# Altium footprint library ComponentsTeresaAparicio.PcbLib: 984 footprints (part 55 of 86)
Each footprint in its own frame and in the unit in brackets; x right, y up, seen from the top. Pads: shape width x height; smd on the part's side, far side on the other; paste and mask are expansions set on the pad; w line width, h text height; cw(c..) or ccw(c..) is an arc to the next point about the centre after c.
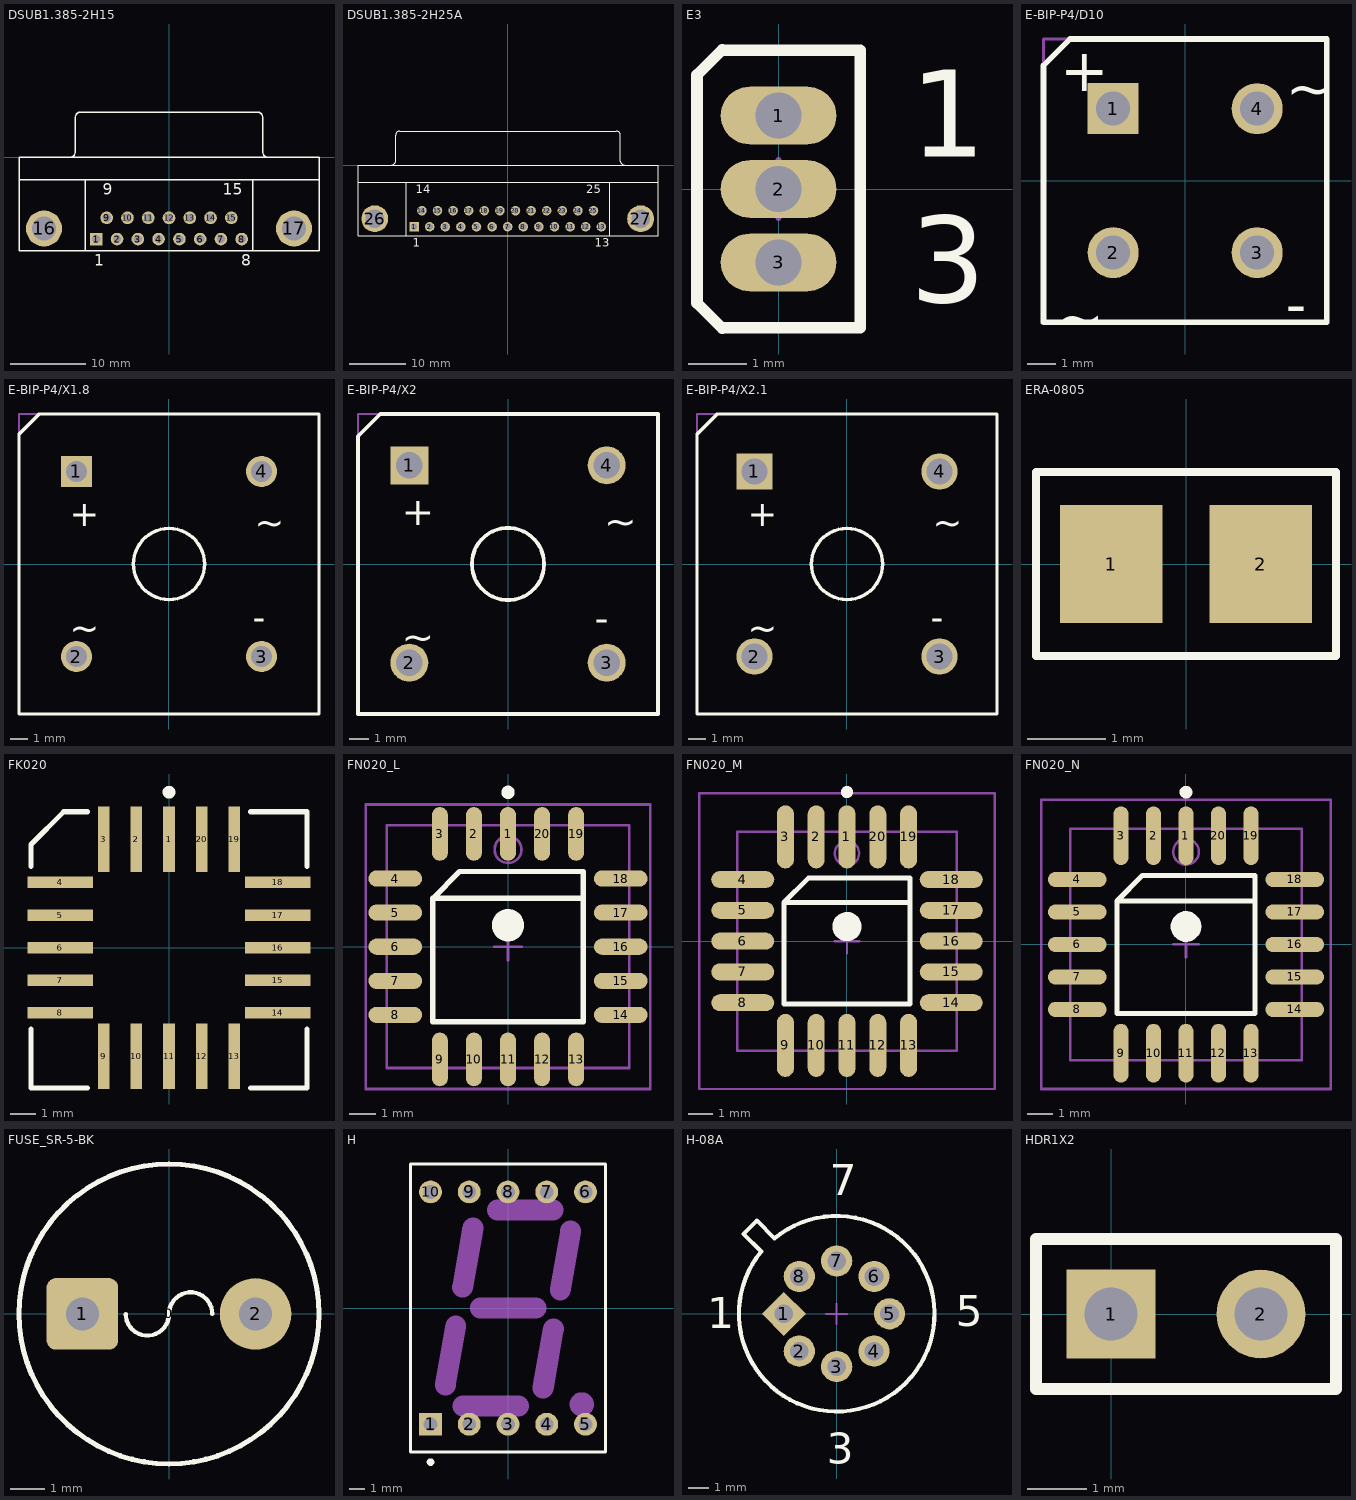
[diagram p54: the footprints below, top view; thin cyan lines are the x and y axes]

## DSUB1.385-2H15 [mm] "Connector; D Subminiature; 15 Position; Right Angle; Pitch 1.385 mm"
height 12.75
pads (17):
  rect 1.69x1.69 hole 1.09: 1(-9.695,-10.92)
  round 1.69 hole 1.09: 2(-6.925,-10.92) 3(-4.155,-10.92) 4(-1.385,-10.92) 5(1.385,-10.92) 6(4.155,-10.92) 7(6.925,-10.92) 8(9.695,-10.92) 9(-8.31,-8.08) 10(-5.54,-8.08) 11(-2.77,-8.08) 12(0,-8.08) 13(2.77,-8.08) 14(5.54,-8.08) 15(8.31,-8.08)
  round 4.8 hole 3.18: 16(-16.66,-9.5) 17(16.66,-9.5)
Top Overlay:
  lines w0.2: -20,-3 20,-3 ; -13.195,0.005 ccw(c-13.195,0.7) -12.5,0.7 -12.5,5.3 ; -12.495,5.305 cw(c-11.8,5.305) -11.8,6 11.8,6 cw(c11.8,5.305) 12.495,5.305 ; -11.14,-12.5 -11.14,-3 ; 11.14,-12.5 11.14,-3 ; 12.5,5.3 12.5,0.7 ccw(c13.195,0.7) 13.195,0.005 ; -20,-12.5 -20,0 20,0 20,-12.5 -20,-12.5
  text "1" at -9.945,-14.475 h1.5
  text "8" at 9.652,-14.475 h1.5
  text "15" at 7.185,-4.975 h1.5
  text "9" at -8.81,-4.975 h1.5

## DSUB1.385-2H25A [mm] "Connector; D Subminiature; 25 Position; Right Angle; Pitch 1.385 mm"
height 12.93
pads (27):
  rect 1.69x1.69 hole 1.09: 1(-16.566,-10.92)
  round 1.69 hole 1.09: 2(-13.805,-10.92) 3(-11.044,-10.92) 4(-8.283,-10.92) 5(-5.522,-10.92) 6(-2.761,-10.92) 7(0,-10.92) 8(2.761,-10.92) 9(5.522,-10.92) 10(8.283,-10.92) 11(11.044,-10.92) 12(13.805,-10.92) 13(16.566,-10.92) 14(-15.185,-8.08) 15(-12.424,-8.08) 16(-9.663,-8.08) 17(-6.902,-8.08) 18(-4.141,-8.08) 19(-1.38,-8.08) 20(1.381,-8.08) 21(4.142,-8.08) 22(6.903,-8.08) 23(9.664,-8.08) 24(12.425,-8.08) 25(15.186,-8.08)
  round 4.76 hole 3.26: 26(-23.526,-9.5) 27(23.526,-9.5)
Top Overlay:
  lines w0.2: -26.496,-3 26.604,-3 ; -20.541,0.005 ccw(c-20.541,0.7) -19.846,0.7 -19.846,5.3 ; -19.841,5.305 cw(c-19.146,5.305) -19.146,6 19.254,6 cw(c19.254,5.305) 19.949,5.305 ; -17.946,-12.5 -17.946,-3 ; 18.054,-12.5 18.054,-3 ; 19.954,5.3 19.954,0.7 ccw(c20.649,0.7) 20.649,0.005 ; -26.496,-12.5 -26.496,0 26.604,0 26.604,-12.5 -26.496,-12.5
  text "25" at 13.936,-4.975 h1.5
  text "14" at -16.31,-4.975 h1.5
  text "13" at 15.441,-14.475 h1.5
  text "1" at -16.816,-14.475 h1.5

## E3 [mm] "TO, Flat Index; 3 In-Line, Axial Leads; Body Dia. 4.6mm; Lead Dia. 0.5 mm (max)"
height 4.01
pads (3):
  oval 2x1 hole 0.8: 1(0,1.27) 2(0,0) 3(0,-1.27)
Top Overlay:
  lines w0.2: -0.97,-2.41 -1.41,-1.97 -1.41,1.97 -0.97,2.41 ; -0.97,-2.4 1.41,-2.4 1.41,2.4 -0.97,2.4
  text "3" at 2.275,-1.963 h1.5
  text "1" at 2.275,0.555 h1.5
Mechanical 15:
  lines w0.1: -0.5,0 0.5,0 ; 0,-0.5 0,0.5

## E-BIP-P4/D10 [mm] "Bridge Rectifier; 4 Terminals; Body 9.4 x 9.4 mm (typ); Pitch 5.08 mm"
height 9.91
pads (4):
  rect 1.8x1.8 hole 1.2: 1(-2.54,2.54)
  round 1.8 hole 1.2: 2(-2.54,-2.54) 3(2.54,-2.54) 4(2.54,2.54)
Top Overlay:
  lines w0.2: -5,-5 5,-5 5,5 -4.064,5 -5,4.064 -5,-5
  text "~" at 3.556,2.54 h1.5
  text "~" at -4.572,-5.588 h1.5
  text "-" at 3.556,-5.08 h1.5
  text "+" at -4.41,3.164 h1.5
Mechanical 13:
  lines w0.1: -5,-5 5,-5 5,5 -5,5 -5,-5
3D body: height 9.91, standoff 0, extent -5,-5 5,5

## E-BIP-P4/X1.8 [mm] "Bridge Rectifier; 4 Terminals; Body 16.8 x 16.8 mm (typ); Pitch 10.67 mm"
height 6.35
pads (4):
  rect 1.8x1.8 hole 1.2: 1(-5.335,5.335)
  round 1.8 hole 1.2: 2(-5.335,-5.335) 3(5.335,-5.335) 4(5.335,5.335)
Top Overlay:
  circle w0.2: c0,0 r2.05
  lines w0.2: -8.65,-8.65 8.65,-8.65 8.65,8.65 -7.474,8.65 -8.65,7.474 -8.65,-8.65
  text "~" at -5.723,-4.437 h1.5
  text "~" at 4.945,1.659 h1.5
  text "-" at 4.825,-3.809 h1.5
  text "+" at -5.723,2.167 h1.5
Mechanical 13:
  lines w0.1: -8.65,-8.65 -8.65,8.65 8.65,8.65 8.65,-8.65 -8.65,-8.65
3D body: height 6.35, standoff 0, extent -8.65,-8.65 8.65,8.65

## E-BIP-P4/X2 [mm] "Bridge Rectifier; 4 Terminals; Body 15.2 x 15.2 mm (typ); Pitch 10.4 mm"
height 5.34
pads (4):
  rect 2x2 hole 1.4: 1(-5.2,5.2)
  round 2 hole 1.4: 2(-5.2,-5.2) 3(5.2,-5.2) 4(5.2,5.2)
Top Overlay:
  circle w0.2: c0,0 r1.9
  lines w0.2: -7.9,-7.9 -7.9,6.724 -6.724,7.9 7.9,7.9 7.9,-7.9 -7.9,-7.9
  text "+" at -5.588,2.032 h1.5
  text "-" at 4.572,-3.556 h1.5
  text "~" at 5.08,1.524 h1.5
  text "~" at -5.588,-4.572 h1.5
Mechanical 13:
  lines w0.1: -7.9,-7.9 -7.9,7.9 7.9,7.9 7.9,-7.9 -7.9,-7.9
3D body: height 5.34, standoff 0, extent -7.9,-7.9 7.9,7.9

## E-BIP-P4/X2.1 [mm] "Bridge Rectifier; 4 Terminals; Body 16.8 x 16.8 mm (typ); Pitch 10.67 mm"
height 6.35
pads (4):
  rect 2.1x2.1 hole 1.5: 1(-5.335,5.335)
  round 2.1 hole 1.5: 2(-5.335,-5.335) 3(5.335,-5.335) 4(5.335,5.335)
Top Overlay:
  circle w0.2: c0,0 r2.05
  lines w0.2: -8.65,-8.65 -8.65,7.474 -7.474,8.65 8.65,8.65 8.65,-8.65 -8.65,-8.65
  text "+" at -5.723,2.167 h1.5
  text "-" at 4.825,-3.809 h1.5
  text "~" at 4.945,1.659 h1.5
  text "~" at -5.723,-4.437 h1.5
Mechanical 13:
  lines w0.1: -8.65,-8.65 8.65,-8.65 8.65,8.65 -8.65,8.65 -8.65,-8.65
3D body: height 6.35, standoff 0, extent -8.65,-8.65 8.65,8.65

## ERA-0805 [mm] "Chip Resistor; Body 2 x 1.3 mm (LxW typ)"
height 0.6
pads (2):
  rect 1.3x1.5 smd: 1(-0.95,0) 2(0.95,0)
Top Overlay:
  lines w0.1: -1.905,-1.168 -1.905,1.168 1.905,1.168 1.905,-1.168 -1.88,-1.168
3D body: height 0.78, standoff 0, extent -1,-0.625 1,0.625

## FK020 [mm] "Leadless Chip Carrier; 20 Terminals; Body 8.9 x 8.9 mm"
height 2.03
pads (20):
  rect 0.45x2.55 smd: 1(0,4.225) 2(-1.27,4.225) 3(-2.54,4.225) 9(-2.54,-4.225) 10(-1.27,-4.225) 11(0,-4.225) 12(1.27,-4.225) 13(2.54,-4.225) 19(2.54,4.225) 20(1.27,4.225)
  rect 2.55x0.45 smd: 4(-4.225,2.54) 5(-4.225,1.27) 6(-4.225,0) 7(-4.225,-1.27) 8(-4.225,-2.54) 14(4.225,-2.54) 15(4.225,-1.27) 16(4.225,0) 17(4.225,1.27) 18(4.225,2.54)
Top Overlay:
  circle w0.25: c0,6.05 r0.125
  lines w0.2: -5.375,-3.165 -5.375,-5.463 -3.165,-5.463 ; -5.375,3.165 -5.375,4.012 -4.1,5.288 -3.165,5.288 ; 3.165,-5.463 5.375,-5.463 5.375,-3.165 ; 3.165,5.288 5.375,5.288 5.375,3.165

## FN020_L [mm] "Leaded Chip Carrier, 20-Leads, Body 9x9mm, Pitch 1.27mm, IPC High Density"
height 4.57
pads (20):
  oval 0.6x2 smd: 1(0,4.2) 2(-1.27,4.2) 3(-2.54,4.2) 9(-2.54,-4.2) 10(-1.27,-4.2) 11(0,-4.2) 12(1.27,-4.2) 13(2.54,-4.2) 19(2.54,4.2) 20(1.27,4.2)
  oval 2x0.6 smd: 4(-4.2,2.54) 5(-4.2,1.27) 6(-4.2,0) 7(-4.2,-1.27) 8(-4.2,-2.54) 14(4.2,-2.54) 15(4.2,-1.27) 16(4.2,0) 17(4.2,1.27) 18(4.2,2.54)
Top Overlay:
  circle w0.25: c0,5.75 r0.125
  circle w0.6: c0,0.8 r0.3
  lines w0.2: 2.8,1.8 -2.8,1.8 ; -2.8,1.8 -1.8,2.8 2.8,2.8 2.8,-2.8 -2.8,-2.8 -2.8,1.8
Mechanical 13:
  circle w0.1: c0,3.62 r0.5
  lines w0.1: -4.52,-4.52 -4.52,4.52 4.52,4.52 4.52,-4.52 -4.52,-4.52
Mechanical 15:
  lines w0.1: -0.5,0 0.5,0 ; 0,-0.5 0,0.5 ; -5.3,-5.3 -5.3,5.3 5.3,5.3 5.3,-5.3 -5.3,-5.3
3D body: height 4.57, standoff 0, extent -4.52,-4.52 4.52,4.52

## FN020_M [mm] "Leaded Chip Carrier, 20-Leads, Body 9x9mm, Pitch 1.27mm, IPC Low Density"
height 4.57
pads (20):
  oval 0.7x2.6 smd: 1(0,4.3) 2(-1.27,4.3) 3(-2.54,4.3) 9(-2.54,-4.3) 10(-1.27,-4.3) 11(0,-4.3) 12(1.27,-4.3) 13(2.54,-4.3) 19(2.54,4.3) 20(1.27,4.3)
  oval 2.6x0.7 smd: 4(-4.3,2.54) 5(-4.3,1.27) 6(-4.3,0) 7(-4.3,-1.27) 8(-4.3,-2.54) 14(4.3,-2.54) 15(4.3,-1.27) 16(4.3,0) 17(4.3,1.27) 18(4.3,2.54)
Top Overlay:
  circle w0.25: c0,6.15 r0.125
  circle w0.6: c0,0.6 r0.3
  lines w0.2: 2.6,1.6 -2.6,1.6 ; -2.6,1.6 -1.6,2.6 2.6,2.6 2.6,-2.6 -2.6,-2.6 -2.6,1.6
Mechanical 13:
  circle w0.1: c0,3.62 r0.5
  lines w0.1: -4.52,-4.52 -4.52,4.52 4.52,4.52 4.52,-4.52 -4.52,-4.52
Mechanical 15:
  lines w0.1: -0.5,0 0.5,0 ; 0,-0.5 0,0.5 ; -6.1,-6.1 -6.1,6.1 6.1,6.1 6.1,-6.1 -6.1,-6.1
3D body: height 4.57, standoff 0, extent -4.52,-4.52 4.52,4.52

## FN020_N [mm] "Leaded Chip Carrier, 20-Leads, Body 9x9mm, Pitch 1.27mm, IPC Medium Density"
height 4.57
pads (20):
  oval 0.6x2.3 smd: 1(0,4.25) 2(-1.27,4.25) 3(-2.54,4.25) 9(-2.54,-4.25) 10(-1.27,-4.25) 11(0,-4.25) 12(1.27,-4.25) 13(2.54,-4.25) 19(2.54,4.25) 20(1.27,4.25)
  oval 2.3x0.6 smd: 4(-4.25,2.54) 5(-4.25,1.27) 6(-4.25,0) 7(-4.25,-1.27) 8(-4.25,-2.54) 14(4.25,-2.54) 15(4.25,-1.27) 16(4.25,0) 17(4.25,1.27) 18(4.25,2.54)
Top Overlay:
  circle w0.6: c0,0.7 r0.3
  circle w0.25: c0,5.95 r0.125
  lines w0.2: 2.7,1.7 -2.7,1.7 ; -2.7,1.7 -2.7,-2.7 2.7,-2.7 2.7,2.7 -1.7,2.7 -2.7,1.7
Mechanical 13:
  circle w0.1: c0,3.62 r0.5
  lines w0.1: -4.52,-4.52 4.52,-4.52 4.52,4.52 -4.52,4.52 -4.52,-4.52
Mechanical 15:
  lines w0.1: -0.5,0 0.5,0 ; 0,-0.5 0,0.5 ; -5.65,-5.65 5.65,-5.65 5.65,5.65 -5.65,5.65 -5.65,-5.65
3D body: height 4.57, standoff 0, extent -4.52,-4.52 4.52,4.52

## FUSE_SR-5-BK [mm]
height 9.3
pads (3):
  round 0.5 on Mech14: 0(0,0)
  rrect25% 2.1x2.1 hole 0.965: 1(-2.54,0)
  round 2.1 hole 0.965: 2(2.54,0)
Top Overlay:
  circle w0.152: c0,0 r4.4
  lines w0.127: -1.27,0 ccw(c-0.635,0) 0,0 cw(c0.635,0) 1.27,0
Mechanical 13:
  circle w0.127: c0,-0.003 r4.4
3D body: height 8.29, standoff -2.55, extent -4.35,-4.321 4.35,4.315

## H [mm] "LED, 7-Segment Display, 14.2 mm, RHD; 10 Leads; Row Space 15.24 mm; Pitch 2.54 mm"
height 8.25
pads (10):
  rect 1.5x1.5 hole 0.9: 1(-5.08,-7.62)
  round 1.5 hole 0.9: 2(-2.54,-7.62) 3(0,-7.62) 4(2.54,-7.62) 5(5.08,-7.62) 6(5.08,7.62) 7(2.54,7.62) 8(0,7.62) 9(-2.54,7.62) 10(-5.08,7.62)
Top Overlay:
  circle w0.25: c-5.08,-10.1 r0.125
  lines w0.2: -6.4,-9.45 6.4,-9.45 6.4,9.45 -6.4,9.45 -6.4,-9.45
Mechanical 1:
  circle w1: c4.842,-6.316 r0.296
  lines w1.37: -4.108,-5.054 -3.425,-1.17 ; -2.974,1.368 -2.293,5.255 ; -2.958,-6.429 0.692,-6.426 ; -1.821,0 1.828,0 ; -0.689,6.425 2.96,6.425 ; 2.295,-5.256 2.98,-1.371 ; 3.427,1.169 4.11,5.058
Mechanical 13:
  lines w0.1: -6.4,-9.45 -6.4,9.45 6.4,9.45 6.4,-9.45 -6.4,-9.45
3D body: height 8.25, standoff 0, extent -6.4,-9.45 6.4,9.45

## H-08A [mm] "Can; 8 Leads; Pin Circle Dia. 5.08 mm; Lead Dia. 0.53 mm (max)"
height 4.7
pads (8):
  rect 1.5x1.5 hole 0.9 rot 45: 1(-2.54,0)
  round 1.5 hole 0.9: 2(-1.796,-1.796) 3(0,-2.54) 4(1.796,-1.796) 5(2.54,0) 6(1.796,1.796) 7(0,2.54) 8(-1.796,1.796)
Top Overlay:
  lines w0.2: -4.475,3.838 -3.626,2.99 ccw(c0,0) -2.99,3.626 -3.838,4.475 -4.475,3.838
  text "7" at -0.332,5.7 h1.5
  text "5" at 5.712,-0.589 h1.5
  text "3" at -0.469,-7.22 h1.5
  text "1" at -6.22,-0.696 h1.5
Mechanical 15:
  lines w0.1: -0.5,0 0.5,0 ; 0,-0.5 0,0.5

## HDR1X2 [mm] "Connector; Header; 2 Position"
pads (2):
  rect 1.5x1.5 hole 0.9: 1(0,0)
  round 1.5 hole 0.9: 2(2.54,0)
Top Overlay:
  lines w0.2: -1.27,-1.27 3.81,-1.27 3.81,1.27 -1.27,1.27 -1.27,-1.27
